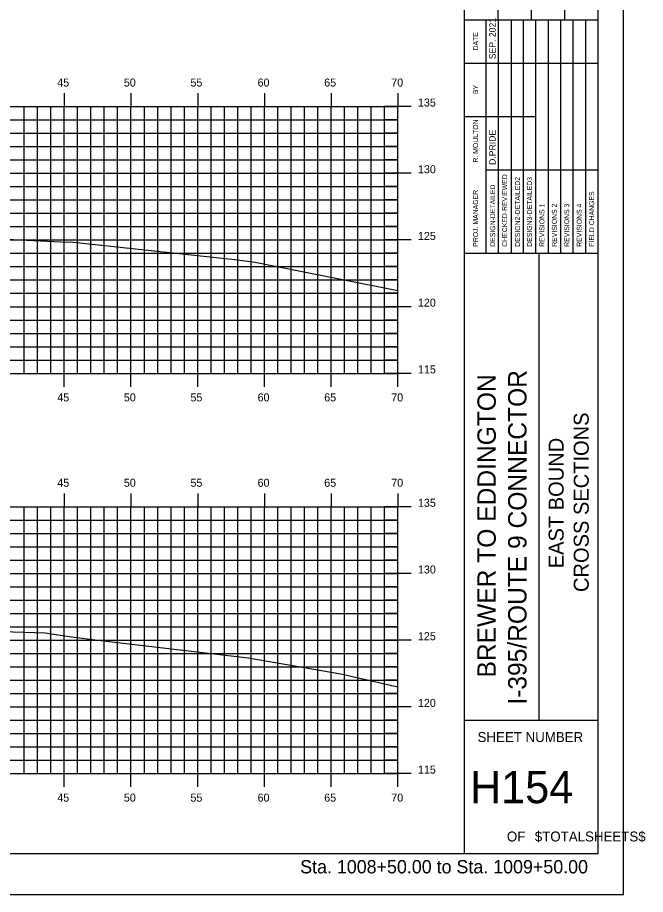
# Model space of a CAD drawing. Extents: x 851960 to 852132, y 365624 to 365734.
# Drawn here: x 852084.8 to 852131.8, y 365624 to 365689.7 of the extents above; entities that cross this region are included whole.
import ezdxf

# ---------------------------------------------------------------- set-up
doc = ezdxf.new("R2010")
doc.units = 0
for name, color, linetype in [('BORDER', 7, 'Continuous'), ('H_V ANNOTATION', 7, 'Continuous'), ('MAJOR', 7, 'Continuous'), ('MINOR', 7, 'Continuous'), ('PLOT BOUNDARY', 7, 'Continuous'), ('S_Roadway_Centerline', 7, 'Continuous')]:
    doc.layers.add(name, color=color, linetype=linetype)

msp = doc.modelspace()

# ---------------------------------------------------------------- linework, layer by layer
at = {"layer": 'BORDER'}
for p, q in [((852118.279, 365627.027), (852118.279, 365732.027)), ((852120.779, 365689.53), (852120.779, 365698.177)), ((852123.279, 365689.53), (852123.279, 365698.177)), ((852125.779, 365689.53), (852125.779, 365698.177)), ((852118.279, 365689.53), (852128.279, 365689.53)), ((852118.279, 365672.03), (852128.279, 365672.03)), ((852123.87, 365637.03), (852123.87, 365672.03)), ((852118.279, 365637.03), (852128.279, 365637.03))]:
    msp.add_line(p, q, dxfattribs=at)
msp.add_lwpolyline([(851968.279, 365627.027), (852128.279, 365627.027), (852128.279, 365732.027), (851968.279, 365732.027)], close=True, dxfattribs=at)
for points in [[(852119.894, 365686.28), (852119.894, 365689.53)], [(852120.826, 365672.033), (852120.826, 365689.53)], [(852121.758, 365689.53), (852121.758, 365672.033)], [(852122.69, 365672.033), (852122.69, 365689.53)], [(852123.621, 365672.033), (852123.621, 365689.53)], [(852124.553, 365672.033), (852124.553, 365689.53)], [(852125.485, 365672.033), (852125.485, 365689.53)], [(852126.416, 365672.033), (852126.416, 365689.53)], [(852127.348, 365672.033), (852127.348, 365689.53)], [(852119.895, 365672.033), (852119.895, 365688.824)], [(852118.279, 365686.28), (852128.279, 365686.28)], [(852118.279, 365682.28), (852119.895, 365682.28)], [(852119.894, 365682.28), (852123.621, 365682.28)], [(852119.894, 365678.28), (852128.279, 365678.28)]]:
    msp.add_lwpolyline(points, dxfattribs=at)
at = {"layer": 'MAJOR'}
for p, q in [((852088.279, 365684.029), (852088.279, 365683.027)), ((852093.279, 365684.029), (852093.279, 365683.027)), ((852098.279, 365684.029), (852098.279, 365683.027)), ((852103.279, 365684.029), (852103.279, 365683.027)), ((852108.279, 365684.029), (852108.279, 365683.027)), ((852113.279, 365684.029), (852113.279, 365683.027)), ((851973.279, 365683.027), (852113.279, 365683.027)), ((851973.279, 365683.027), (852113.279, 365683.027)), ((852088.279, 365663.027), (852088.279, 365683.027)), ((852093.279, 365663.027), (852093.279, 365683.027)), ((852098.279, 365663.027), (852098.279, 365683.027)), ((852103.279, 365663.027), (852103.279, 365683.027)), ((852108.279, 365663.027), (852108.279, 365683.027)), ((852114.281, 365683.027), (852112.277, 365683.027)), ((852113.279, 365663.027), (852113.279, 365683.027)), ((852113.279, 365663.027), (852113.279, 365683.027)), ((851973.279, 365678.027), (852113.279, 365678.027)), ((852114.281, 365678.027), (852112.277, 365678.027)), ((851973.279, 365673.027), (852113.279, 365673.027)), ((852114.281, 365673.027), (852112.277, 365673.027)), ((851973.279, 365668.027), (852113.279, 365668.027)), ((852114.281, 365668.027), (852112.277, 365668.027)), ((851973.279, 365663.027), (852113.279, 365663.027)), ((851973.279, 365663.027), (852113.279, 365663.027)), ((852088.279, 365662.025), (852088.279, 365663.027)), ((852093.279, 365662.025), (852093.279, 365663.027)), ((852098.279, 365662.025), (852098.279, 365663.027)), ((852103.279, 365662.025), (852103.279, 365663.027)), ((852108.279, 365662.025), (852108.279, 365663.027)), ((852114.281, 365663.027), (852112.277, 365663.027)), ((852113.279, 365662.025), (852113.279, 365663.027)), ((852088.279, 365654.029), (852088.279, 365653.027)), ((852093.279, 365654.029), (852093.279, 365653.027)), ((852098.279, 365654.029), (852098.279, 365653.027)), ((852103.279, 365654.029), (852103.279, 365653.027)), ((852108.279, 365654.029), (852108.279, 365653.027)), ((852113.279, 365654.029), (852113.279, 365653.027)), ((851973.279, 365653.027), (852113.279, 365653.027)), ((851973.279, 365653.027), (852113.279, 365653.027)), ((852088.279, 365633.027), (852088.279, 365653.027)), ((852093.279, 365633.027), (852093.279, 365653.027)), ((852098.279, 365633.027), (852098.279, 365653.027)), ((852103.279, 365633.027), (852103.279, 365653.027)), ((852108.279, 365633.027), (852108.279, 365653.027)), ((852114.281, 365653.027), (852112.277, 365653.027)), ((852113.279, 365633.027), (852113.279, 365653.027)), ((852113.279, 365633.027), (852113.279, 365653.027)), ((851973.279, 365648.027), (852113.279, 365648.027)), ((852114.281, 365648.027), (852112.277, 365648.027)), ((851973.279, 365643.027), (852113.279, 365643.027)), ((852114.281, 365643.027), (852112.277, 365643.027)), ((851973.279, 365638.027), (852113.279, 365638.027)), ((852114.281, 365638.027), (852112.277, 365638.027)), ((851973.279, 365633.027), (852113.279, 365633.027)), ((851973.279, 365633.027), (852113.279, 365633.027)), ((852088.279, 365632.025), (852088.279, 365633.027)), ((852093.279, 365632.025), (852093.279, 365633.027)), ((852098.279, 365632.025), (852098.279, 365633.027)), ((852103.279, 365632.025), (852103.279, 365633.027)), ((852108.279, 365632.025), (852108.279, 365633.027)), ((852114.281, 365633.027), (852112.277, 365633.027)), ((852113.279, 365632.025), (852113.279, 365633.027))]:
    msp.add_line(p, q, dxfattribs=at)
at = {"layer": 'MINOR'}
for p, q in [((852085.279, 365663.027), (852085.279, 365683.027)), ((852086.279, 365663.027), (852086.279, 365683.027)), ((852087.279, 365663.027), (852087.279, 365683.027)), ((852089.279, 365663.027), (852089.279, 365683.027)), ((852090.279, 365663.027), (852090.279, 365683.027)), ((852091.279, 365663.027), (852091.279, 365683.027)), ((852092.279, 365663.027), (852092.279, 365683.027)), ((852094.279, 365663.027), (852094.279, 365683.027)), ((852095.279, 365663.027), (852095.279, 365683.027)), ((852096.279, 365663.027), (852096.279, 365683.027)), ((852097.279, 365663.027), (852097.279, 365683.027)), ((852099.279, 365663.027), (852099.279, 365683.027)), ((852100.279, 365663.027), (852100.279, 365683.027)), ((852101.279, 365663.027), (852101.279, 365683.027)), ((852102.279, 365663.027), (852102.279, 365683.027)), ((852104.279, 365663.027), (852104.279, 365683.027)), ((852105.279, 365663.027), (852105.279, 365683.027)), ((852106.279, 365663.027), (852106.279, 365683.027)), ((852107.279, 365663.027), (852107.279, 365683.027)), ((852109.279, 365663.027), (852109.279, 365683.027)), ((852110.279, 365663.027), (852110.279, 365683.027)), ((852111.279, 365663.027), (852111.279, 365683.027)), ((852112.279, 365663.027), (852112.279, 365683.027)), ((851973.279, 365682.027), (852113.279, 365682.027)), ((852113.279, 365682.027), (852112.277, 365682.027)), ((851973.279, 365681.027), (852113.279, 365681.027)), ((852113.279, 365681.027), (852112.277, 365681.027)), ((851973.279, 365680.027), (852113.279, 365680.027)), ((852113.279, 365680.027), (852112.277, 365680.027)), ((851973.279, 365679.027), (852113.279, 365679.027)), ((852113.279, 365679.027), (852112.277, 365679.027)), ((851973.279, 365677.027), (852113.279, 365677.027)), ((852113.279, 365677.027), (852112.277, 365677.027)), ((851973.279, 365676.027), (852113.279, 365676.027)), ((852113.279, 365676.027), (852112.277, 365676.027)), ((851973.279, 365675.027), (852113.279, 365675.027)), ((852113.279, 365675.027), (852112.277, 365675.027)), ((851973.279, 365674.027), (852113.279, 365674.027)), ((852113.279, 365674.027), (852112.277, 365674.027)), ((851973.279, 365672.027), (852113.279, 365672.027)), ((852113.279, 365672.027), (852112.277, 365672.027)), ((851973.279, 365671.027), (852113.279, 365671.027)), ((852113.279, 365671.027), (852112.277, 365671.027)), ((851973.279, 365670.027), (852113.279, 365670.027)), ((852113.279, 365670.027), (852112.277, 365670.027)), ((851973.279, 365669.027), (852113.279, 365669.027)), ((852113.279, 365669.027), (852112.277, 365669.027)), ((851973.279, 365667.027), (852113.279, 365667.027)), ((852113.279, 365667.027), (852112.277, 365667.027)), ((851973.279, 365666.027), (852113.279, 365666.027)), ((852113.279, 365666.027), (852112.277, 365666.027)), ((851973.279, 365665.027), (852113.279, 365665.027)), ((852113.279, 365665.027), (852112.277, 365665.027)), ((851973.279, 365664.027), (852113.279, 365664.027)), ((852113.279, 365664.027), (852112.277, 365664.027)), ((852085.279, 365633.027), (852085.279, 365653.027)), ((852086.279, 365633.027), (852086.279, 365653.027)), ((852087.279, 365633.027), (852087.279, 365653.027)), ((852089.279, 365633.027), (852089.279, 365653.027)), ((852090.279, 365633.027), (852090.279, 365653.027)), ((852091.279, 365633.027), (852091.279, 365653.027)), ((852092.279, 365633.027), (852092.279, 365653.027)), ((852094.279, 365633.027), (852094.279, 365653.027)), ((852095.279, 365633.027), (852095.279, 365653.027)), ((852096.279, 365633.027), (852096.279, 365653.027)), ((852097.279, 365633.027), (852097.279, 365653.027)), ((852099.279, 365633.027), (852099.279, 365653.027)), ((852100.279, 365633.027), (852100.279, 365653.027)), ((852101.279, 365633.027), (852101.279, 365653.027)), ((852102.279, 365633.027), (852102.279, 365653.027)), ((852104.279, 365633.027), (852104.279, 365653.027)), ((852105.279, 365633.027), (852105.279, 365653.027)), ((852106.279, 365633.027), (852106.279, 365653.027)), ((852107.279, 365633.027), (852107.279, 365653.027)), ((852109.279, 365633.027), (852109.279, 365653.027)), ((852110.279, 365633.027), (852110.279, 365653.027)), ((852111.279, 365633.027), (852111.279, 365653.027)), ((852112.279, 365633.027), (852112.279, 365653.027)), ((851973.279, 365652.027), (852113.279, 365652.027)), ((852113.279, 365652.027), (852112.277, 365652.027)), ((851973.279, 365651.027), (852113.279, 365651.027)), ((852113.279, 365651.027), (852112.277, 365651.027)), ((851973.279, 365650.027), (852113.279, 365650.027)), ((852113.279, 365650.027), (852112.277, 365650.027)), ((851973.279, 365649.027), (852113.279, 365649.027)), ((852113.279, 365649.027), (852112.277, 365649.027)), ((851973.279, 365647.027), (852113.279, 365647.027)), ((852113.279, 365647.027), (852112.277, 365647.027)), ((851973.279, 365646.027), (852113.279, 365646.027)), ((852113.279, 365646.027), (852112.277, 365646.027)), ((851973.279, 365645.027), (852113.279, 365645.027)), ((852113.279, 365645.027), (852112.277, 365645.027)), ((851973.279, 365644.027), (852113.279, 365644.027)), ((852113.279, 365644.027), (852112.277, 365644.027)), ((851973.279, 365642.027), (852113.279, 365642.027)), ((852113.279, 365642.027), (852112.277, 365642.027)), ((851973.279, 365641.027), (852113.279, 365641.027)), ((852113.279, 365641.027), (852112.277, 365641.027)), ((851973.279, 365640.027), (852113.279, 365640.027)), ((852113.279, 365640.027), (852112.277, 365640.027)), ((851973.279, 365639.027), (852113.279, 365639.027)), ((852113.279, 365639.027), (852112.277, 365639.027)), ((851973.279, 365637.027), (852113.279, 365637.027)), ((852113.279, 365637.027), (852112.277, 365637.027)), ((851973.279, 365636.027), (852113.279, 365636.027)), ((852113.279, 365636.027), (852112.277, 365636.027)), ((851973.279, 365635.027), (852113.279, 365635.027)), ((852113.279, 365635.027), (852112.277, 365635.027)), ((851973.279, 365634.027), (852113.279, 365634.027)), ((852113.279, 365634.027), (852112.277, 365634.027))]:
    msp.add_line(p, q, dxfattribs=at)
at = {"layer": 'PLOT BOUNDARY'}
msp.add_lwpolyline([(851960.186, 365623.968), (852130.186, 365623.968), (852130.186, 365733.968), (851960.186, 365733.968)], close=True, dxfattribs=at)
at = {"layer": 'S_Roadway_Centerline'}
for points in [[(852022.178, 365669.718), (852039.605, 365672.002), (852041.639, 365672.256), (852042.244, 365672.337), (852045.2, 365672.758), (852046.319, 365672.812), (852061.426, 365673.397), (852064.162, 365673.412), (852067.719, 365673.448), (852068.232, 365673.445), (852073.739, 365673.386), (852081.376, 365673.205), (852088.518, 365672.867), (852088.754, 365672.888), (852099.895, 365671.68), (852101.06, 365671.555), (852102.582, 365671.375), (852105.106, 365670.856), (852113.279, 365669.238)], [(852032.313, 365641.267), (852046.057, 365643.213), (852048.797, 365643.52), (852050.265, 365643.55), (852060.208, 365643.782), (852066.129, 365643.91), (852066.28, 365643.93), (852074.212, 365643.956), (852077.434, 365643.941), (852079.573, 365643.815), (852086.849, 365643.591), (852088.814, 365643.281), (852090.788, 365643.024), (852102.051, 365641.698), (852109, 365640.503), (852113.279, 365639.529)]]:
    msp.add_lwpolyline(points, dxfattribs=at)

# ---------------------------------------------------------------- texts
at = {"layer": 'BORDER'}
for s, height, p in [('SEP. 2021', 0.4845, (852120.602, 365686.575)), ('DATE', 0.3714, (852119.283, 365687.235)), ('BY', 0.3714, (852119.283, 365683.965)), ('R. MOULTON', 0.3727, (852119.283, 365678.832)), ('D.PRIDE', 0.4845, (852120.602, 365678.653)), ('CHECKED-REVIEWED', 0.37275, (852121.46, 365672.518)), ('DESIGN2-DETAILED2', 0.37275, (852122.429, 365672.518)), ('DESIGN3-DETAILED3', 0.37275, (852123.323, 365672.518)), ('DESIGN-DETAILED', 0.37275, (852120.566, 365672.518)), ('PROJ. MANAGER', 0.37275, (852119.283, 365672.518)), ('FIELD CHANGES', 0.37275, (852127.982, 365672.518)), ('REVISIONS 1', 0.37275, (852124.255, 365672.518)), ('REVISIONS 2', 0.37275, (852125.187, 365672.518)), ('REVISIONS 3', 0.37275, (852126.118, 365672.518)), ('REVISIONS 4', 0.37275, (852127.05, 365672.518)), ('I-395/ROUTE 9 CONNECTOR', 1.37787, (852122.914, 365638.192)), ('BREWER TO EDDINGTON', 1.37787, (852120.613, 365640.231)), ('CROSS SECTIONS', 1.125, (852127.576, 365646.638)), ('EAST BOUND', 1.125, (852125.697, 365648.418))]:
    msp.add_text(s, height=height, rotation=90, dxfattribs=at).set_placement(p)
for s, height, p in [('SHEET NUMBER', 0.74527, (852119.244, 365635.393)), ('H154', 2.4194, (852118.68, 365630.809)), ('$TOTALSHEETS$', 0.74527, (852123.535, 365627.94)), ('OF', 0.7453, (852121.446, 365627.94))]:
    msp.add_text(s, height=height, dxfattribs=at).set_placement(p)
at = {"layer": 'H_V ANNOTATION'}
for s, height, p in [('45', 0.6, (852087.757, 365684.527)), ('50', 0.6, (852092.743, 365684.527)), ('55', 0.6, (852097.735, 365684.527)), ('60', 0.6, (852102.765, 365684.527)), ('65', 0.6, (852107.757, 365684.527)), ('70', 0.6, (852112.781, 365684.527)), ('135', 0.6, (852114.779, 365683.027)), ('130', 0.6, (852114.779, 365678.027)), ('125', 0.6, (852114.779, 365673.027)), ('120', 0.6, (852114.779, 365668.027)), ('115', 0.6, (852114.779, 365663.027)), ('45', 0.6, (852087.757, 365660.927)), ('50', 0.6, (852092.743, 365660.927)), ('55', 0.6, (852097.735, 365660.927)), ('60', 0.6, (852102.765, 365660.927)), ('65', 0.6, (852107.757, 365660.927)), ('70', 0.6, (852112.781, 365660.927)), ('45', 0.6, (852087.757, 365654.527)), ('50', 0.6, (852092.743, 365654.527)), ('55', 0.6, (852097.735, 365654.527)), ('60', 0.6, (852102.765, 365654.527)), ('65', 0.6, (852107.757, 365654.527)), ('70', 0.6, (852112.781, 365654.527)), ('135', 0.6, (852114.779, 365653.027)), ('130', 0.6, (852114.779, 365648.027)), ('125', 0.6, (852114.779, 365643.027)), ('120', 0.6, (852114.779, 365638.027)), ('115', 0.6, (852114.779, 365633.027)), ('45', 0.6, (852087.757, 365630.927)), ('50', 0.6, (852092.743, 365630.927)), ('55', 0.6, (852097.735, 365630.927)), ('60', 0.6, (852102.765, 365630.927)), ('65', 0.6, (852107.757, 365630.927)), ('70', 0.6, (852112.781, 365630.927)), ('Sta. 1008+50.00 to Sta. 1009+50.00', 1.0002, (852105.955, 365625.547))]:
    msp.add_text(s, height=height, dxfattribs=at).set_placement(p)

doc.saveas('drawing.dxf')
